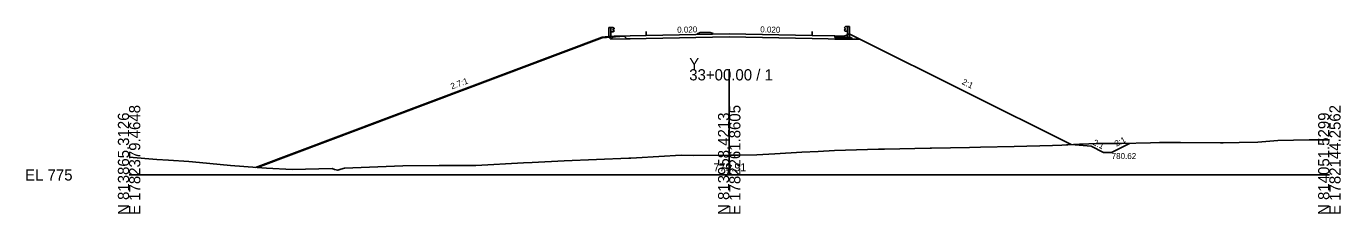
# Model space of a CAD drawing. Extents: x -12583 to 5303, y -44 to 25667.
# Drawn here: x 1974.3 to 2302.8, y 3490.3 to 3537.2 of the extents above; entities that cross this region are included whole.
import ezdxf

# ---------------------------------------------------------------- set-up
doc = ezdxf.new("R2010")
doc.units = 0
for name, color, linetype in [('Exist Cross Section Cell', 7, 'Continuous'), ('Exist XS Center Line Elevation Label', 7, 'Continuous'), ('Exist XS Ground Line', 7, 'Continuous'), ('Prop Conc 5in Monolithic Surface Mount Island', 7, 'Continuous'), ('Prop XS DDE', 7, 'Continuous'), ('Prop XS Ditch Standard Text', 7, 'Continuous'), ('Prop XS Dump Level', 7, 'Continuous'), ('Prop XS Earthwork Shape', 7, 'Continuous'), ('Prop XS EOT Tick Mark', 7, 'Continuous'), ('Prop XS Finish Grade', 7, 'Continuous'), ('Prop XS Finish Grade CurbGutter', 7, 'Continuous'), ('Prop XS Finish Grade Earthwork', 7, 'Continuous'), ('Prop XS Finish Grade Paved Shoulder', 7, 'Continuous'), ('Prop XS Finish Grade Pavement', 7, 'Continuous'), ('Prop XS Guardrail', 7, 'Continuous'), ('Prop XS Pvmt Edge Slope', 7, 'Continuous'), ('Prop XS SE Text', 7, 'Continuous'), ('Prop XS Side Slope Text', 7, 'Continuous'), ('Prop XS Subgrade CurbGutter', 7, 'Continuous'), ('Prop XS Subgrade Earthwork', 7, 'Continuous')]:
    doc.layers.add(name, color=color, linetype=linetype)

msp = doc.modelspace()

# ---------------------------------------------------------------- linework, layer by layer
at = {"layer": 'Exist Cross Section Cell'}
for p, q in [((2150, 3500), (2150, 3526.43)), ((2000, 3500), (2150, 3500)), ((2150, 3500), (2300, 3500))]:
    msp.add_line(p, q, dxfattribs=at)
at = {"layer": 'Exist XS Ground Line'}
for p, q in [((2287.11, 3508.6), (2294.94, 3508.78)), ((2294.94, 3508.78), (2299.27, 3508.75)), ((2299.27, 3508.75), (2300, 3508.81)), ((2161.43, 3505.3), (2168.13, 3505.72)), ((2168.13, 3505.72), (2172.25, 3505.9)), ((2172.25, 3505.9), (2176.33, 3506.09)), ((2176.33, 3506.09), (2187.35, 3506.42)), ((2187.35, 3506.42), (2188.78, 3506.43)), ((2188.78, 3506.43), (2200.24, 3506.7)), ((2200.24, 3506.7), (2200.57, 3506.72)), ((2200.57, 3506.72), (2210.07, 3506.88)), ((2210.07, 3506.88), (2212.79, 3506.97)), ((2212.79, 3506.97), (2221.19, 3507.08)), ((2221.19, 3507.08), (2230.78, 3507.4)), ((2230.78, 3507.4), (2233.14, 3507.44)), ((2233.14, 3507.44), (2237.59, 3507.7)), ((2237.59, 3507.7), (2242.2, 3507.82)), ((2242.2, 3507.82), (2248.08, 3507.82)), ((2248.08, 3507.82), (2255.31, 3508.03)), ((2255.31, 3508.03), (2257.51, 3508.11)), ((2257.51, 3508.11), (2262.81, 3508.1)), ((2262.81, 3508.1), (2272.81, 3508.01)), ((2272.81, 3508.01), (2273.42, 3508.06)), ((2273.42, 3508.06), (2277.5, 3508.08)), ((2277.5, 3508.08), (2282.11, 3508.23)), ((2282.11, 3508.23), (2287.11, 3508.6)), ((2000, 3504.47), (2006.97, 3503.89)), ((2006.97, 3503.89), (2009.89, 3503.7)), ((2009.89, 3503.7), (2014.96, 3503.35)), ((2014.96, 3503.35), (2017.56, 3503.15)), ((2017.56, 3503.15), (2025.32, 3502.39)), ((2025.32, 3502.39), (2032.03, 3501.85)), ((2053.86, 3501.73), (2068.41, 3502.27)), ((2068.41, 3502.27), (2077.52, 3502.39)), ((2077.52, 3502.39), (2086.63, 3502.36)), ((2086.63, 3502.36), (2098.62, 3503.05)), ((2098.62, 3503.05), (2100.72, 3503.14)), ((2100.72, 3503.14), (2108.78, 3503.54)), ((2108.78, 3503.54), (2124.91, 3504.17)), ((2124.91, 3504.17), (2125.44, 3504.19)), ((2125.44, 3504.19), (2126.86, 3504.29)), ((2126.86, 3504.29), (2137.96, 3504.92)), ((2137.96, 3504.92), (2140.95, 3504.9)), ((2140.95, 3504.9), (2150, 3504.91)), ((2150, 3504.91), (2152.35, 3504.92)), ((2152.35, 3504.92), (2156.93, 3505.02)), ((2156.93, 3505.02), (2161.43, 3505.3)), ((2032.03, 3501.85), (2034.32, 3501.7)), ((2034.32, 3501.7), (2040.8, 3501.38)), ((2040.8, 3501.38), (2050.8, 3501.58)), ((2050.8, 3501.58), (2051.34, 3501.37)), ((2051.34, 3501.37), (2052.16, 3501.17)), ((2052.16, 3501.17), (2052.95, 3501.46)), ((2052.95, 3501.46), (2053.86, 3501.73))]:
    msp.add_line(p, q, dxfattribs=at)
at = {"layer": 'Prop Conc 5in Monolithic Surface Mount Island'}
for p, q in [((2142, 3535.31), (2142.74, 3535.57)), ((2142, 3535.14), (2142, 3535.31)), ((2142.74, 3535.57), (2143.99, 3535.62)), ((2145.24, 3535.62), (2143.99, 3535.62)), ((2146, 3535.39), (2145.24, 3535.62)), ((2146, 3535.22), (2146, 3535.39))]:
    msp.add_line(p, q, dxfattribs=at)
at = {"layer": 'Prop XS DDE'}
for p, q in [((2235.48, 3507.58), (2240.48, 3507.16)), ((2240.48, 3507.16), (2243.56, 3505.62)), ((2243.56, 3505.62), (2245.56, 3505.62)), ((2250.08, 3507.88), (2245.56, 3505.62))]:
    msp.add_line(p, q, dxfattribs=at)
at = {"layer": 'Prop XS Dump Level'}
for p, q in [((2129.25, 3534.88), (2150, 3535.3)), ((2150, 3535.3), (2170.75, 3534.88))]:
    msp.add_line(p, q, dxfattribs=at)
at = {"layer": 'Prop XS Earthwork Shape'}
msp.add_lwpolyline([(2188.78, 3506.43), (2200.24, 3506.7), (2200.57, 3506.72), (2210.07, 3506.88), (2212.79, 3506.97), (2221.19, 3507.08), (2230.78, 3507.4), (2233.14, 3507.44), (2235.48, 3507.58), (2182.68, 3533.98), (2180.81, 3533.98), (2176.42, 3533.98), (2174.75, 3534.01), (2170.75, 3534.09), (2150, 3534.51), (2129.25, 3534.09), (2125.25, 3534.01), (2124.44, 3534), (2123.75, 3534.68), (2118.25, 3534.24), (2032.13, 3501.85), (2034.32, 3501.7), (2040.8, 3501.38), (2050.8, 3501.58), (2051.34, 3501.37), (2052.16, 3501.17), (2052.95, 3501.46), (2053.86, 3501.73), (2068.41, 3502.27), (2077.52, 3502.39), (2086.63, 3502.36), (2098.62, 3503.05), (2100.72, 3503.14), (2108.78, 3503.54), (2124.91, 3504.17), (2125.44, 3504.19), (2126.86, 3504.29), (2137.96, 3504.92), (2140.95, 3504.9), (2150, 3504.91), (2152.35, 3504.92), (2156.93, 3505.02), (2161.43, 3505.3), (2168.13, 3505.72), (2172.25, 3505.9), (2176.33, 3506.09), (2187.35, 3506.42)], close=True, dxfattribs=at)
at = {"layer": 'Prop XS EOT Tick Mark'}
for p, q in [((2129.25, 3534.88), (2129.25, 3535.88)), ((2170.75, 3534.88), (2170.75, 3535.88))]:
    msp.add_line(p, q, dxfattribs=at)
at = {"layer": 'Prop XS Finish Grade'}
for p, q in [((2179.44, 3535.02), (2180.02, 3535.31)), ((2182.68, 3533.98), (2180.02, 3535.31)), ((2121.25, 3534.72), (2119.75, 3534.6))]:
    msp.add_line(p, q, dxfattribs=at)
at = {"layer": 'Prop XS Finish Grade CurbGutter'}
for p, q in [((2178.75, 3534.68), (2179.44, 3535.02)), ((2176.42, 3534.77), (2178.75, 3534.68))]:
    msp.add_line(p, q, dxfattribs=at)
at = {"layer": 'Prop XS Finish Grade Earthwork'}
for p, q in [((2118.25, 3534.48), (2031.6, 3501.89)), ((2118.25, 3534.48), (2119.75, 3534.6)), ((2182.68, 3533.98), (2235.48, 3507.58))]:
    msp.add_line(p, q, dxfattribs=at)
at = {"layer": 'Prop XS Finish Grade Paved Shoulder'}
for p, q in [((2129.25, 3534.88), (2121.25, 3534.72)), ((2170.75, 3534.88), (2176.42, 3534.77))]:
    msp.add_line(p, q, dxfattribs=at)
at = {"layer": 'Prop XS Finish Grade Pavement'}
for p, q in [((2129.25, 3534.88), (2150, 3535.3)), ((2150, 3535.3), (2170.75, 3534.88)), ((2150, 3535.3), (2170.75, 3534.88))]:
    msp.add_line(p, q, dxfattribs=at)
at = {"layer": 'Prop XS Guardrail'}
for p, q in [((2119.93, 3536.88), (2120.43, 3536.88)), ((2119.93, 3534.38), (2119.93, 3536.88)), ((2120.43, 3536.88), (2120.93, 3536.88)), ((2120.43, 3536.88), (2120.43, 3534.38)), ((2120.93, 3535.74), (2120.43, 3535.74)), ((2120.93, 3536.88), (2121.22, 3536.68)), ((2121.22, 3536.56), (2120.93, 3536.36)), ((2120.93, 3536.36), (2120.93, 3536.26)), ((2120.93, 3536.26), (2121.22, 3536.06)), ((2121.22, 3535.94), (2120.93, 3535.74)), ((2121.22, 3536.68), (2121.25, 3536.62)), ((2121.25, 3536.62), (2121.22, 3536.56)), ((2121.22, 3536.06), (2121.25, 3536)), ((2121.25, 3536), (2121.22, 3535.94)), ((2178.78, 3536.87), (2178.75, 3536.81)), ((2178.75, 3536.81), (2178.78, 3536.75)), ((2178.78, 3536.26), (2178.75, 3536.2)), ((2178.75, 3536.2), (2178.78, 3536.14)), ((2179.07, 3537.07), (2178.78, 3536.87)), ((2178.78, 3536.75), (2179.07, 3536.55)), ((2179.07, 3536.46), (2178.78, 3536.26)), ((2178.78, 3536.14), (2179.07, 3535.94)), ((2179.57, 3537.07), (2179.07, 3537.07)), ((2179.07, 3536.55), (2179.07, 3536.46)), ((2179.07, 3535.94), (2179.57, 3535.94)), ((2180.07, 3537.07), (2179.57, 3537.07)), ((2179.57, 3537.07), (2179.57, 3534.57)), ((2180.07, 3534.57), (2180.07, 3537.07))]:
    msp.add_line(p, q, dxfattribs=at)
at = {"layer": 'Prop XS Pvmt Edge Slope'}
for p, q in [((2121.25, 3534.72), (2120.44, 3533.92)), ((2179.44, 3534.35), (2180.44, 3534.35)), ((2180.44, 3534.35), (2180.81, 3533.98))]:
    msp.add_line(p, q, dxfattribs=at)
at = {"layer": 'Prop XS Subgrade CurbGutter'}
for p, q in [((2179.44, 3534.35), (2179.44, 3535.02)), ((2176.42, 3534.77), (2176.42, 3534.35)), ((2176.42, 3534.35), (2179.44, 3534.35))]:
    msp.add_line(p, q, dxfattribs=at)
at = {"layer": 'Prop XS Subgrade Earthwork'}
for p, q in [((2120.44, 3533.92), (2119.75, 3534.6)), ((2125.25, 3534.01), (2120.44, 3533.92)), ((2129.25, 3534.09), (2125.25, 3534.01)), ((2150, 3534.51), (2129.25, 3534.09)), ((2170.75, 3534.09), (2150, 3534.51)), ((2170.75, 3534.09), (2174.75, 3534.01)), ((2174.75, 3534.01), (2176.42, 3533.98)), ((2176.42, 3533.98), (2176.42, 3533.98)), ((2176.42, 3533.98), (2180.81, 3533.98)), ((2180.81, 3533.98), (2182.68, 3533.98))]:
    msp.add_line(p, q, dxfattribs=at)

# ---------------------------------------------------------------- texts
at = {"layer": 'Exist Cross Section Cell'}
for s, p in [('Y', (2140, 3526.43)), ('33+00.00 / 1', (2140, 3523.63)), ('EL 775', (1974, 3498.6))]:
    msp.add_text(s, height=2.8, dxfattribs=at).set_placement(p)
for s, p in [('N 813865.3126', (2000, 3490)), ('E 1782379.4648', (2002.8, 3490)), ('N 813958.4213', (2150, 3490)), ('E 1782261.8605', (2152.8, 3490)), ('N 814051.5299', (2300, 3490)), ('E 1782144.2562', (2302.8, 3490))]:
    msp.add_text(s, height=2.8, rotation=90, dxfattribs=at).set_placement(p)
at = {"layer": 'Exist XS Center Line Elevation Label'}
msp.add_text('779.91', height=2, dxfattribs=at).set_placement((2146.08, 3500.91))
at = {"layer": 'Prop XS Ditch Standard Text'}
msp.add_text('780.62', height=1.5, dxfattribs=at).set_placement((2245.59, 3503.97))
at = {"layer": 'Prop XS Dump Level'}
for p in [(2121.25, 3534.44), (2176.42, 3534.73)]:
    msp.add_text('Case2', height=0.04, dxfattribs=at).set_placement(p)
at = {"layer": 'Prop XS SE Text'}
for rotation, p in [(1.1458, (2137, 3535.54)), (358.8542, (2157.75, 3535.64)), (358.8542, (2157.75, 3535.64))]:
    msp.add_text('0.020', height=1.5, rotation=rotation, dxfattribs=at).set_placement(p)
at = {"layer": 'Prop XS Side Slope Text'}
for s, rotation, p in [('2.7:1', 20.1266, (2080.69, 3521.38)), ('2:1', 333.4349, (2208.02, 3522.78)), ('2:1', 333.4349, (2240.75, 3507.63)), ('2:1', 26.5651, (2246.79, 3507.03))]:
    msp.add_text(s, height=1.5, rotation=rotation, dxfattribs=at).set_placement(p)

doc.saveas('drawing.dxf')
